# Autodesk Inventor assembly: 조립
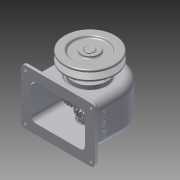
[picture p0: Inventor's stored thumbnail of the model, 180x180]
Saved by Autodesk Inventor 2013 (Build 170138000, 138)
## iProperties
Created: 2016-01
Part Number: 조립
Document SubType Name: Assembly
Designer: dgall
Author: dgall
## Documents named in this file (16)
- C:\Users\dgall\Desktop\460105V1027\조립.iam
- C:\Users\dgall\Desktop\460105V1027\V-벨트풀리.ipt
- C:\Users\dgall\Desktop\460105V1027\뒤커버.ipt
- C:\Users\dgall\Desktop\460105V1027\멈춤나사 - M4x10.ipt
- C:\Users\dgall\Desktop\460105V1027\베어링 6203.ipt
- C:\Users\dgall\Desktop\460105V1027\본체.ipt
- C:\Users\dgall\Desktop\460105V1027\볼트 M3 x 8.ipt
- C:\Users\dgall\Desktop\460105V1027\볼트 M3 x 10.ipt
- C:\Users\dgall\Desktop\460105V1027\부시1.ipt
- C:\Users\dgall\Desktop\460105V1027\부시2.ipt
- C:\Users\dgall\Desktop\460105V1027\스퍼기어.ipt
- C:\Users\dgall\Desktop\460105V1027\앞커버.ipt
- C:\Users\dgall\Desktop\460105V1027\오일씰 28 40 8.ipt
- C:\Users\dgall\Desktop\460105V1027\축.ipt
- C:\Users\dgall\Desktop\460105V1027\키 - 5 x 5 x 18.ipt
- C:\Users\dgall\Desktop\460105V1027\키 - 6 x 6 x 22.ipt
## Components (9 placed, 3 different names)
1. V-벨트풀리:1
2. ISO 4762 M3 x 10:1
3. ISO 4762 M3 x 10:2
4. ISO 4762 M3 x 10:3
5. ISO 4762 M3 x 10:4
6. ISO 4762 M3 x 8:1
7. ISO 4762 M3 x 8:2
8. ISO 4762 M3 x 8:3
9. ISO 4762 M3 x 8:4
